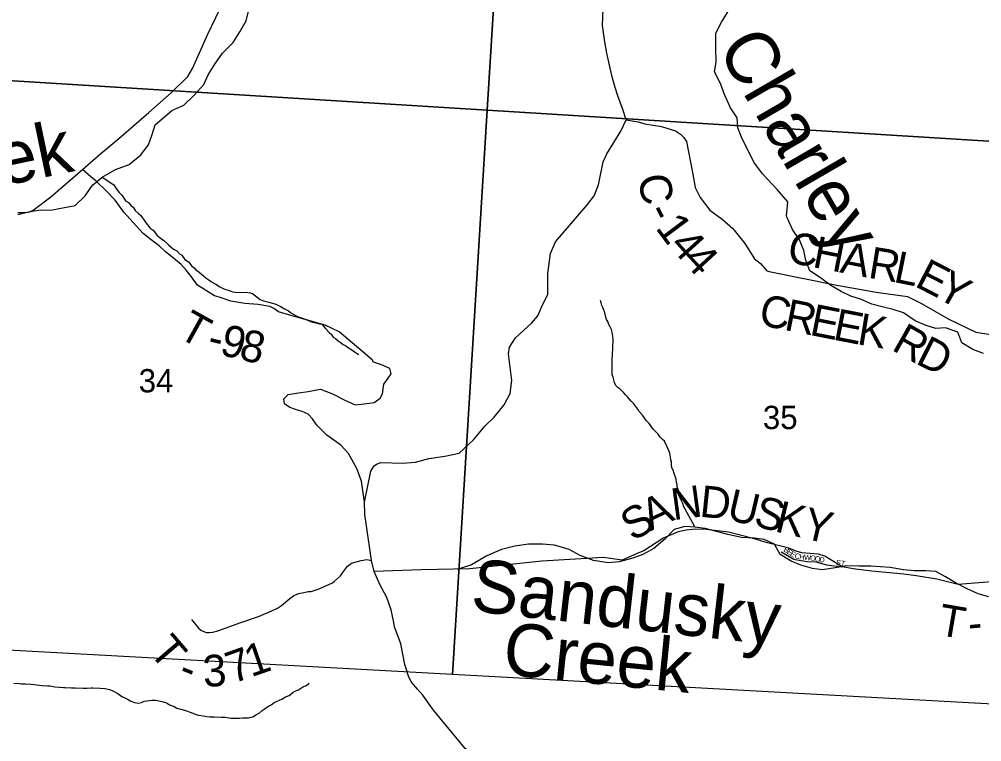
# Model space of a CAD drawing. Extents: x 1949938.81 to 1949945.61, y 152207.65 to 152214.09.
# Drawn here: x 1949942.704 to 1949944.431, y 152208.942 to 152210.239 of the extents above; entities that cross this region are included whole.
import ezdxf

# ---------------------------------------------------------------- set-up
doc = ezdxf.new("R2010")
doc.units = 0
for name, color, linetype in [('GM_X_County_Road', 7, 'Continuous'), ('GM_X_County_Road_Text', 7, 'Continuous'), ('GM_X_Minor_River', 7, 'Continuous'), ('GM_X_Minor_River_Text', 7, 'Continuous'), ('GM_X_Section', 7, 'Continuous'), ('GM_X_Section_Text', 7, 'Continuous'), ('GM_X_Township_Road', 7, 'Continuous'), ('GM_X_Township_Road_Text', 7, 'Continuous'), ('GM_X_Township_ROW', 7, 'Continuous'), ('GM_X_Township_Subdivision', 7, 'Continuous'), ('GM_X_Township_Subdivision_Text', 7, 'Continuous')]:
    doc.layers.add(name, color=color, linetype=linetype)

msp = doc.modelspace()

# ---------------------------------------------------------------- linework, layer by layer
at = {"layer": 'GM_X_County_Road'}
for points in [[(1949943.7934, 152210.0582), (1949943.7863, 152210.0783), (1949943.778, 152210.1014), (1949943.7733, 152210.1163), (1949943.7689, 152210.1332), (1949943.7647, 152210.1506), (1949943.7587, 152210.1777), (1949943.7547, 152210.198), (1949943.7505, 152210.2272), (1949943.7528, 152210.2879), (1949943.7786, 152210.3293), (1949943.7948, 152210.3533), (1949943.8062, 152210.3875), (1949943.8062, 152210.4156), (1949943.7956, 152210.4457), (1949943.785, 152210.4643), (1949943.7804, 152210.4757), (1949943.7778, 152210.4892)], [(1949942.701, 152209.8916), (1949942.7151, 152209.8919), (1949942.7228, 152209.893), (1949942.7289, 152209.8959), (1949942.7605, 152209.9201), (1949942.8172, 152209.9689), (1949942.8501, 152209.9978), (1949942.8823, 152210.0244), (1949942.9365, 152210.0712), (1949942.977, 152210.1069), (1949943.0063, 152210.1361), (1949943.015, 152210.1501), (1949943.0419, 152210.2106), (1949943.0716, 152210.2729)], [(1949943.3761, 152209.156), (1949943.3716, 152209.1787), (1949943.3635, 152209.201), (1949943.3508, 152209.2238), (1949943.3407, 152209.2476), (1949943.3363, 152209.2672), (1949943.327, 152209.3291), (1949943.3243, 152209.3496), (1949943.3233, 152209.3717), (1949943.3346, 152209.4276), (1949943.3406, 152209.4371), (1949943.3449, 152209.4401), (1949943.3529, 152209.4429), (1949943.3919, 152209.4421), (1949943.415, 152209.4437), (1949943.4392, 152209.4503), (1949943.4676, 152209.4544), (1949943.4933, 152209.4597), (1949943.5191, 152209.484), (1949943.5403, 152209.5087), (1949943.5562, 152209.5243), (1949943.5744, 152209.5467), (1949943.585, 152209.5672), (1949943.588, 152209.59), (1949943.582, 152209.6379), (1949943.5835, 152209.65), (1949943.5945, 152209.6667), (1949943.6233, 152209.6929), (1949943.6346, 152209.7066), (1949943.643, 152209.726), (1949943.6524, 152209.7446), (1949943.6524, 152209.7826), (1949943.6574, 152209.8183), (1949943.6661, 152209.8393), (1949943.724, 152209.9059), (1949943.7355, 152209.9215), (1949943.7433, 152209.9413), (1949943.7516, 152209.983), (1949943.7584, 152209.997), (1949943.7835, 152210.0379), (1949943.7934, 152210.0582)], [(1949943.7934, 152210.0582), (1949943.8147, 152210.0543), (1949943.8269, 152210.0512), (1949943.8563, 152210.0462), (1949943.8818, 152210.0382), (1949943.8907, 152210.0327), (1949943.8969, 152210.0267), (1949943.9016, 152210.0192), (1949943.9129, 152209.9606), (1949943.9171, 152209.9366), (1949943.926, 152209.9189), (1949943.9435, 152209.8957), (1949943.9656, 152209.8796), (1949943.9845, 152209.8628), (1949944.0063, 152209.8364), (1949944.0238, 152209.8089), (1949944.0282, 152209.8052)], [(1949944.0282, 152209.8052), (1949944.0345, 152209.8), (1949944.0456, 152209.7872), (1949944.0501, 152209.7862)], [(1949944.0501, 152209.7862), (1949944.1712, 152209.7615), (1949944.2418, 152209.7486), (1949944.2979, 152209.7412), (1949944.3233, 152209.7286), (1949944.371, 152209.7008), (1949944.421, 152209.6768), (1949944.4748, 152209.6684)], [(1949943.6692, 152208.6533), (1949943.6622, 152208.679), (1949943.6518, 152208.7014), (1949943.6305, 152208.7301), (1949943.6093, 152208.7583), (1949943.5891, 152208.7822), (1949943.5622, 152208.843), (1949943.5524, 152208.8851), (1949943.5493, 152208.8969), (1949943.5414, 152208.9094), (1949943.5289, 152208.9166), (1949943.5175, 152208.9227), (1949943.5043, 152208.9299), (1949943.4471, 152208.9983), (1949943.4285, 152209.0254), (1949943.4187, 152209.0361), (1949943.4074, 152209.0495), (1949943.4025, 152209.0598), (1949943.3956, 152209.0803), (1949943.3888, 152209.1174), (1949943.3776, 152209.1483), (1949943.3761, 152209.156)]]:
    msp.add_lwpolyline(points, dxfattribs=at)
at = {"layer": 'GM_X_Minor_River'}
for points in [[(1949943.9548, 152210.1617), (1949943.9541, 152210.1868), (1949943.9542, 152210.2134), (1949943.9642, 152210.2332), (1949943.9748, 152210.2506), (1949943.9802, 152210.2712), (1949943.9826, 152210.2902), (1949943.9872, 152210.3114), (1949943.9941, 152210.3297), (1949943.9843, 152210.348), (1949943.9669, 152210.3602), (1949943.9488, 152210.3762), (1949943.9315, 152210.3877), (1949943.9156, 152210.4022)], [(1949942.701, 152209.8881), (1949942.723, 152209.8933), (1949942.7427, 152209.8963), (1949942.7601, 152209.8962), (1949942.7851, 152209.9007), (1949942.8041, 152209.9044), (1949942.8223, 152209.9219), (1949942.8353, 152209.9408), (1949942.8527, 152209.9552), (1949942.8763, 152209.9688), (1949942.9013, 152209.9778), (1949942.9218, 152209.9952), (1949942.9355, 152210.0134), (1949942.9424, 152210.0316), (1949942.9478, 152210.0491), (1949942.9774, 152210.0749), (1949942.9994, 152210.0847), (1949943.0169, 152210.1021), (1949943.0352, 152210.1218), (1949943.0428, 152210.1392), (1949943.055, 152210.1582), (1949943.0687, 152210.1779), (1949943.0877, 152210.1969), (1949943.0999, 152210.2158), (1949943.1114, 152210.2356), (1949943.116, 152210.2553)], [(1949944.4344, 152209.639), (1949944.4155, 152209.6459), (1949944.3959, 152209.6581), (1949944.3884, 152209.6772), (1949944.3664, 152209.6849), (1949944.349, 152209.6834), (1949944.3316, 152209.6888), (1949944.312, 152209.6972), (1949944.2908, 152209.7117), (1949944.2727, 152209.7179), (1949944.2552, 152209.7218), (1949944.2341, 152209.7272), (1949944.2137, 152209.7364), (1949944.1963, 152209.7418), (1949944.1789, 152209.7502), (1949944.1607, 152209.7609), (1949944.1419, 152209.7747), (1949944.123, 152209.7869), (1949944.1155, 152209.8059), (1949944.1118, 152209.8234), (1949944.1043, 152209.8425), (1949944.0915, 152209.8615), (1949944.0809, 152209.8851), (1949944.0833, 152209.911), (1949944.0645, 152209.9331), (1949944.0381, 152209.9614), (1949944.0223, 152209.982), (1949944.0125, 152210.0018), (1949944.0012, 152210.0239), (1949943.9937, 152210.0437), (1949943.9923, 152210.0619), (1949943.9802, 152210.0795), (1949943.9697, 152210.1038), (1949943.9622, 152210.1236), (1949943.9517, 152210.1442), (1949943.9548, 152210.1617)], [(1949942.8527, 152209.9552), (1949942.8738, 152209.9415), (1949942.8763, 152209.9369), (1949942.8793, 152209.9326), (1949942.8826, 152209.9284), (1949942.8871, 152209.9237), (1949942.8897, 152209.9203), (1949942.8948, 152209.9126), (1949942.9001, 152209.9095), (1949942.9045, 152209.9037), (1949942.9083, 152209.9013), (1949942.912, 152209.8956), (1949942.9179, 152209.8901), (1949942.922, 152209.8863), (1949942.9242, 152209.8828), (1949942.9283, 152209.8782), (1949942.9316, 152209.8728), (1949942.9387, 152209.8639), (1949942.9443, 152209.86), (1949942.9517, 152209.85), (1949942.9558, 152209.8473), (1949942.9596, 152209.8442), (1949942.9629, 152209.8422), (1949942.9685, 152209.8368), (1949942.9719, 152209.8337), (1949942.9808, 152209.8259), (1949942.9865, 152209.8232), (1949942.9917, 152209.8178), (1949942.9954, 152209.8154), (1949943.001, 152209.8073), (1949943.0073, 152209.8034), (1949943.0136, 152209.7953), (1949943.0177, 152209.7922), (1949943.0215, 152209.788), (1949943.026, 152209.7852), (1949943.0312, 152209.7814), (1949943.0345, 152209.7779), (1949943.0386, 152209.7744), (1949943.0443, 152209.7712), (1949943.0488, 152209.7674), (1949943.0544, 152209.7646), (1949943.0581, 152209.7626), (1949943.0626, 152209.7591), (1949943.0713, 152209.7548), (1949943.0746, 152209.7536), (1949943.0792, 152209.7524), (1949943.0833, 152209.7508), (1949943.0867, 152209.7496), (1949943.0916, 152209.7488), (1949943.1143, 152209.7484), (1949943.1181, 152209.7479), (1949943.1223, 152209.7467), (1949943.1279, 152209.7421), (1949943.1361, 152209.7354), (1949943.1421, 152209.7334), (1949943.1519, 152209.731), (1949943.1583, 152209.729), (1949943.1625, 152209.7278), (1949943.167, 152209.7262), (1949943.1722, 152209.7238), (1949943.1786, 152209.7195), (1949943.1872, 152209.7152), (1949943.1906, 152209.7121), (1949943.2034, 152209.705), (1949943.2124, 152209.7022), (1949943.2188, 152209.6998), (1949943.2267, 152209.6959), (1949943.2308, 152209.6947), (1949943.2384, 152209.693), (1949943.2425, 152209.6922), (1949943.2471, 152209.6913), (1949943.2537, 152209.6836), (1949943.2604, 152209.6759), (1949943.2638, 152209.6732), (1949943.2675, 152209.6678), (1949943.2716, 152209.6654), (1949943.2761, 152209.6612), (1949943.2798, 152209.6588), (1949943.2854, 152209.6546), (1949943.2896, 152209.653), (1949943.2929, 152209.6502), (1949943.3008, 152209.6452), (1949943.3057, 152209.642), (1949943.3135, 152209.6367)], [(1949943.9162, 152209.3279), (1949943.8992, 152209.3593), (1949943.8966, 152209.3635), (1949943.8948, 152209.3692), (1949943.8923, 152209.3742), (1949943.8883, 152209.3827), (1949943.8872, 152209.388), (1949943.8869, 152209.3926), (1949943.8848, 152209.3994), (1949943.8845, 152209.4036), (1949943.8838, 152209.4074), (1949943.8831, 152209.4132), (1949943.8795, 152209.4231), (1949943.8773, 152209.4292), (1949943.8751, 152209.4334), (1949943.8748, 152209.4391), (1949943.8745, 152209.4437), (1949943.8735, 152209.4479), (1949943.8728, 152209.4529), (1949943.8718, 152209.4601), (1949943.866, 152209.4724), (1949943.8619, 152209.4812), (1949943.8575, 152209.4847), (1949943.8545, 152209.4885), (1949943.8504, 152209.4939), (1949943.846, 152209.4986), (1949943.8419, 152209.5032), (1949943.8345, 152209.5132), (1949943.8296, 152209.5178), (1949943.8222, 152209.5282), (1949943.8163, 152209.5344), (1949943.8141, 152209.5386), (1949943.8071, 152209.5483), (1949943.8022, 152209.5529), (1949943.7952, 152209.5614), (1949943.7918, 152209.5645), (1949943.7888, 152209.5683), (1949943.7825, 152209.5745), (1949943.7788, 152209.5769), (1949943.7747, 152209.5811), (1949943.7721, 152209.5865), (1949943.7696, 152209.596), (1949943.7678, 152209.6003), (1949943.7679, 152209.6067), (1949943.7681, 152209.6151), (1949943.7678, 152209.6223), (1949943.7683, 152209.6272), (1949943.7685, 152209.6379), (1949943.7694, 152209.6474), (1949943.7697, 152209.6641), (1949943.7694, 152209.6698), (1949943.768, 152209.6771), (1949943.767, 152209.682), (1949943.7644, 152209.6866), (1949943.7622, 152209.6905), (1949943.76, 152209.6962), (1949943.7578, 152209.7), (1949943.7567, 152209.7042), (1949943.7546, 152209.7119), (1949943.7517, 152209.7199), (1949943.7495, 152209.7249), (1949943.7485, 152209.7295), (1949943.747, 152209.7341)], [(1949944.444, 152209.202), (1949944.4251, 152209.2074), (1949944.4054, 152209.2166), (1949944.3843, 152209.2273), (1949944.3661, 152209.238), (1949944.3488, 152209.2472), (1949944.3313, 152209.2488), (1949944.3109, 152209.2489), (1949944.2912, 152209.2505), (1949944.267, 152209.2544), (1949944.2496, 152209.256), (1949944.2322, 152209.2568), (1949944.211, 152209.2569), (1949944.189, 152209.2577), (1949944.1685, 152209.254), (1949944.1458, 152209.2503), (1949944.1276, 152209.2526), (1949944.1064, 152209.2588), (1949944.0891, 152209.2657), (1949944.0694, 152209.2779), (1949944.0596, 152209.2962), (1949944.0407, 152209.3046), (1949944.0233, 152209.307), (1949943.9999, 152209.3086), (1949943.9756, 152209.314), (1949943.9348, 152209.3248), (1949943.9166, 152209.3271), (1949943.8984, 152209.328), (1949943.8795, 152209.3227), (1949943.8628, 152209.3053), (1949943.843, 152209.2887), (1949943.8233, 152209.2781), (1949943.8051, 152209.2713), (1949943.7808, 152209.2646), (1949943.7611, 152209.2632), (1949943.7346, 152209.2671), (1949943.7104, 152209.2763), (1949943.6908, 152209.287), (1949943.6643, 152209.2947), (1949943.6431, 152209.2963), (1949943.6181, 152209.2964), (1949943.5931, 152209.2927), (1949943.5696, 152209.2867), (1949943.543, 152209.2754), (1949943.5157, 152209.2595), (1949943.4952, 152209.2528), (1949943.4899, 152209.2513)], [(1949942.6941, 152209.0467), (1949942.7043, 152209.0462), (1949942.7081, 152209.0458), (1949942.7153, 152209.046), (1949942.7247, 152209.0451), (1949942.7308, 152209.0446), (1949942.735, 152209.0442), (1949942.7452, 152209.0428), (1949942.7546, 152209.0423), (1949942.7588, 152209.0422), (1949942.7679, 152209.0406), (1949942.7758, 152209.0397), (1949942.783, 152209.0395), (1949942.7864, 152209.0391), (1949942.7974, 152209.0389), (1949942.8042, 152209.0388), (1949942.8186, 152209.0382), (1949942.8254, 152209.038), (1949942.8326, 152209.0387), (1949942.836, 152209.0386), (1949942.8489, 152209.038), (1949942.858, 152209.0375), (1949942.8659, 152209.0355), (1949942.8708, 152209.0339), (1949942.8805, 152209.0287)], [(1949942.8805, 152209.0287), (1949942.888, 152209.0233), (1949942.8921, 152209.0213), (1949942.8993, 152209.0174), (1949942.9038, 152209.0147), (1949942.9109, 152209.0123), (1949942.9143, 152209.0115), (1949942.9177, 152209.011), (1949942.9231, 152209.0124), (1949942.928, 152209.0146), (1949942.9333, 152209.0153), (1949942.9417, 152209.0163), (1949942.9481, 152209.0162), (1949942.9519, 152209.0157), (1949942.9598, 152209.0141), (1949942.9662, 152209.0125), (1949942.9696, 152209.0109), (1949942.9734, 152209.0082), (1949942.982, 152209.0054), (1949942.9869, 152209.0022), (1949942.9963, 152208.9998), (1949943.002, 152208.9978), (1949943.0121, 152208.9946), (1949943.0197, 152208.9914), (1949943.0257, 152208.9898), (1949943.0348, 152208.9885), (1949943.0408, 152208.9873), (1949943.0461, 152208.9864), (1949943.0544, 152208.9866), (1949943.0665, 152208.9861), (1949943.0734, 152208.9859), (1949943.0843, 152208.9842), (1949943.0991, 152208.984), (1949943.1048, 152208.9846), (1949943.115, 152208.9848), (1949943.1184, 152208.9855), (1949943.1241, 152208.9873), (1949943.1287, 152208.9903), (1949943.1345, 152208.9929), (1949943.1399, 152208.9981), (1949943.1433, 152209.0003), (1949943.1498, 152209.0051), (1949943.1559, 152209.0081), (1949943.1613, 152209.0125), (1949943.1754, 152209.0184), (1949943.1816, 152209.0224), (1949943.1881, 152209.025), (1949943.1919, 152209.028), (1949943.1957, 152209.0306), (1949943.2003, 152209.0335), (1949943.2049, 152209.0353), (1949943.2087, 152209.0376), (1949943.2141, 152209.0409), (1949943.2194, 152209.0427), (1949943.2244, 152209.0472)]]:
    msp.add_lwpolyline(points, dxfattribs=at)
at = {"layer": 'GM_X_Section'}
for points in [[(1949943.6063, 152211.0859), (1949943.5439, 152210.0754), (1949942.4221, 152210.1447), (1949942.4891, 152211.1555)], [(1949944.7104, 152211.0185), (1949944.6567, 152210.0065), (1949943.5439, 152210.0754), (1949943.6063, 152211.0859)], [(1949942.4221, 152210.1447), (1949943.5439, 152210.0754), (1949943.4815, 152209.0627), (1949942.3551, 152209.1241)], [(1949943.5439, 152210.0754), (1949944.6567, 152210.0065), (1949944.6037, 152209.0009), (1949943.4815, 152209.0627)]]:
    msp.add_lwpolyline(points, close=True, dxfattribs=at)
at = {"layer": 'GM_X_Township_Road'}
for points in [[(1949943.3233, 152209.3717), (1949943.318, 152209.4094), (1949943.3099, 152209.4326), (1949943.2948, 152209.4595), (1949943.2813, 152209.4741), (1949943.2559, 152209.4919), (1949943.2382, 152209.5098), (1949943.2303, 152209.5217), (1949943.2224, 152209.5296), (1949943.2118, 152209.5349), (1949943.2012, 152209.5375), (1949943.1894, 152209.5415), (1949943.1801, 152209.5481), (1949943.1788, 152209.5573), (1949943.1867, 152209.5653), (1949943.2052, 152209.5679), (1949943.2223, 152209.5706), (1949943.2448, 152209.5745), (1949943.2659, 152209.5666), (1949943.2883, 152209.5547), (1949943.3068, 152209.5468), (1949943.3227, 152209.5481), (1949943.3411, 152209.5507), (1949943.3517, 152209.5586), (1949943.3556, 152209.5666), (1949943.3583, 152209.5837), (1949943.3662, 152209.5943), (1949943.3715, 152209.6022), (1949943.3688, 152209.6115), (1949943.3543, 152209.6181), (1949943.3398, 152209.6234), (1949943.3372, 152209.6275), (1949943.3169, 152209.6446), (1949943.2782, 152209.6776), (1949943.2527, 152209.6897), (1949943.2211, 152209.6987), (1949943.1814, 152209.7099), (1949943.1692, 152209.7134), (1949943.1606, 152209.7195), (1949943.1533, 152209.7229), (1949943.1328, 152209.7268), (1949943.1085, 152209.7282), (1949943.0837, 152209.7326), (1949943.0628, 152209.7396), (1949943.054, 152209.7425), (1949943.0235, 152209.7612), (1949943.0127, 152209.7765), (1949943.0039, 152209.7878), (1949942.9943, 152209.7983), (1949942.9778, 152209.812), (1949942.9666, 152209.8212), (1949942.9547, 152209.8317), (1949942.9406, 152209.8425), (1949942.9264, 152209.8543), (1949942.9081, 152209.8736), (1949942.8917, 152209.8926), (1949942.876, 152209.9137), (1949942.8604, 152209.9301), (1949942.8417, 152209.9483), (1949942.8324, 152209.9559), (1949942.8172, 152209.9689)], [(1949944.314, 152209.2394), (1949944.2913, 152209.2429), (1949944.234, 152209.2479), (1949944.2009, 152209.2524), (1949944.1811, 152209.2556), (1949944.1498, 152209.2752), (1949944.1387, 152209.2788), (1949944.1086, 152209.281), (1949944.0986, 152209.2839), (1949944.0854, 152209.2895), (1949944.047, 152209.2991), (1949944.0212, 152209.3067), (1949943.977, 152209.318), (1949943.9367, 152209.3229), (1949943.9178, 152209.3234), (1949943.9011, 152209.3219), (1949943.8867, 152209.3189), (1949943.8666, 152209.31), (1949943.8598, 152209.3072), (1949943.859, 152209.3067)], [(1949943.859, 152209.3067), (1949943.8247, 152209.2848), (1949943.8171, 152209.2814)], [(1949943.0131, 152209.1615), (1949943.0256, 152209.146), (1949943.0312, 152209.1416), (1949943.0395, 152209.1382), (1949943.0448, 152209.1378), (1949943.0514, 152209.1385), (1949943.0605, 152209.1411), (1949943.0754, 152209.1465), (1949943.1, 152209.1554), (1949943.1333, 152209.1667), (1949943.1573, 152209.1769), (1949943.1675, 152209.1817), (1949943.1746, 152209.1865), (1949943.1892, 152209.1992), (1949943.1959, 152209.2038), (1949943.205, 152209.2079), (1949943.2145, 152209.2099), (1949943.2221, 152209.2113), (1949943.228, 152209.2115), (1949943.2402, 152209.216), (1949943.2488, 152209.2192), (1949943.2658, 152209.2272), (1949943.2696, 152209.2298), (1949943.2802, 152209.2394), (1949943.2859, 152209.2477), (1949943.293, 152209.257), (1949943.3003, 152209.2621), (1949943.3173, 152209.2672), (1949943.3276, 152209.2691), (1949943.3363, 152209.2672)], [(1949944.7506, 152208.9526), (1949944.7487, 152208.9768), (1949944.7349, 152209.0276), (1949944.7295, 152209.0509), (1949944.7184, 152209.0767), (1949944.7055, 152209.1178), (1949944.6813, 152209.1508), (1949944.6655, 152209.1684), (1949944.6417, 152209.1882), (1949944.6201, 152209.1978), (1949944.5886, 152209.2059), (1949944.5485, 152209.2155), (1949944.493, 152209.2301), (1949944.449, 152209.2287), (1949944.3888, 152209.2243), (1949944.3508, 152209.2338), (1949944.314, 152209.2394)]]:
    msp.add_lwpolyline(points, dxfattribs=at)
at = {"layer": 'GM_X_Township_ROW'}
msp.add_lwpolyline([(1949943.8171, 152209.2814), (1949943.786, 152209.2676), (1949943.7526, 152209.2724), (1949943.642, 152209.266), (1949943.5128, 152209.252), (1949943.4255, 152209.2503), (1949943.3407, 152209.2476)], dxfattribs=at)
at = {"layer": 'GM_X_Township_Subdivision'}
for points in [[(1949944.0713, 152209.283), (1949944.0941, 152209.2695), (1949944.0963, 152209.2691)], [(1949944.0963, 152209.2691), (1949944.1183, 152209.2651), (1949944.1337, 152209.2647), (1949944.1527, 152209.2596), (1949944.1811, 152209.2556)]]:
    msp.add_lwpolyline(points, dxfattribs=at)

# ---------------------------------------------------------------- texts
at = {"layer": 'GM_X_County_Road_Text'}
for s, rotation, p in [('C', 281.0116, (1949943.8137, 152209.9557)), ('-', 297.482, (1949943.8284, 152209.8931)), ('1', 306.6969, (1949943.8445, 152209.864)), ('4', 312.074, (1949943.8691, 152209.8314)), ('C', 348.9598, (1949944.08, 152209.8031)), ('H', 348.9613, (1949944.1258, 152209.7942)), ('4', 312.6817, (1949943.893, 152209.8049)), ('A', 349.0826, (1949944.1751, 152209.7846)), ('R', 350.7598, (1949944.2259, 152209.7748)), ('L', 348.625, (1949944.2714, 152209.7674)), ('E', 332.6884, (1949944.3092, 152209.7604)), ('Y', 330.5426, (1949944.3465, 152209.7412)), ('C', 348.7522, (1949944.0291, 152209.6905)), ('R', 348.7573, (1949944.0749, 152209.6814)), ('E', 348.8095, (1949944.1207, 152209.6723)), ('E', 349.0241, (1949944.1627, 152209.664)), ('K', 350.5196, (1949944.206, 152209.6556)), ('R', 330.4794, (1949944.2676, 152209.6461)), ('D', 333.0207, (1949944.3106, 152209.6218))]:
    msp.add_text(s, height=0.0568, rotation=rotation, dxfattribs=at).set_placement(p)
at = {"layer": 'GM_X_Minor_River_Text'}
for s, height, rotation, p in [('Charley', 0.09482, 300.1349, (1949943.9554, 152210.1873)), ('Creek', 0.0947, 11.8017, (1949942.4743, 152209.8973)), ('Sandusky', 0.0947, 353.5222, (1949943.5121, 152209.1771)), ('Creek', 0.0947, 354.2984, (1949943.5694, 152209.0629))]:
    msp.add_text(s, height=height, rotation=rotation, dxfattribs=at).set_placement(p)
at = {"layer": 'GM_X_Section_Text'}
for s, p in [('34', (1949942.9182, 152209.5689)), ('35', (1949944.0386, 152209.503))]:
    msp.add_text(s, height=0.04186, rotation=0, dxfattribs=at).set_placement(p)
at = {"layer": 'GM_X_Township_Road_Text'}
for s, rotation, p in [('T', 330.9661, (1949942.9861, 152209.6693)), ('9', 346.1881, (1949943.0616, 152209.6372)), ('8', 346.664, (1949943.0961, 152209.6287)), ('-', 346.6821, (1949943.039, 152209.6426)), ('N', 7.7095, (1949943.8777, 152209.3393)), ('D', 354.0919, (1949943.9237, 152209.346)), ('U', 346.897, (1949943.9716, 152209.3411)), ('A', 25.0376, (1949943.8367, 152209.3194)), ('S', 345.3553, (1949944.0199, 152209.3299)), ('K', 346.404, (1949944.058, 152209.3199)), ('S', 31.0386, (1949943.8053, 152209.3004)), ('Y', 347.008, (1949944.1073, 152209.308)), ('T', 350.2894, (1949944.3509, 152209.1339)), ('-', 5.4829, (1949944.4091, 152209.1261)), ('T', 310.5121, (1949942.9349, 152209.1028)), ('1', 18.9887, (1949943.1198, 152209.0574)), ('3', 3.5534, (1949943.035, 152209.04)), ('7', 19.6877, (1949943.087, 152209.0457)), ('-', 337.6153, (1949942.986, 152209.0534))]:
    msp.add_text(s, height=0.0568, rotation=rotation, dxfattribs=at).set_placement(p)
at = {"layer": 'GM_X_Township_Subdivision_Text'}
for s, rotation, p in [('B', 327.4065, (1949944.0746, 152209.2845)), ('E', 327.3956, (1949944.0809, 152209.2804)), ('E', 327.4082, (1949944.0865, 152209.2768)), ('C', 342.2462, (1949944.0946, 152209.2721)), ('H', 352.2884, (1949944.1035, 152209.2694)), ('W', 353.725, (1949944.112, 152209.2683)), ('O', 355.2262, (1949944.123, 152209.2671)), ('O', 350.1793, (1949944.1311, 152209.2664)), ('D', 345.5396, (1949944.1391, 152209.265)), ('ST', 348.6895, (1949944.169, 152209.2597))]:
    msp.add_text(s, height=0.00947, rotation=rotation, dxfattribs=at).set_placement(p)

doc.saveas('drawing.dxf')
